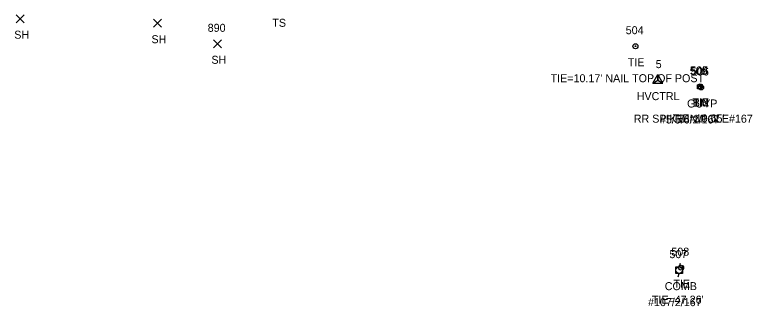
# Model space of a CAD drawing. Extents: x 1879695 to 1880991, y 836466 to 845172.
# Drawn here: x 1880139.2 to 1880323.5, y 843938.5 to 844011.4 of the extents above; entities that cross this region are included whole.
import ezdxf

# ---------------------------------------------------------------- set-up
doc = ezdxf.new("R2010")
doc.units = 0
for name, color, linetype in [('C_A', 7, 'Continuous'), ('C_C', 7, 'Continuous'), ('C_I', 7, 'Continuous'), ('CBP', 7, 'Continuous'), ('CPBM', 7, 'Continuous'), ('CPSM', 7, 'Continuous'), ('L_A', 7, 'Continuous'), ('L_I', 7, 'Continuous'), ('L_TIC', 7, 'Continuous'), ('U_A', 7, 'Continuous'), ('U_C', 7, 'Continuous'), ('U_I', 7, 'Continuous'), ('UP', 7, 'Continuous'), ('UPGW', 7, 'Continuous')]:
    doc.layers.add(name, color=color, linetype=linetype)

msp = doc.modelspace()

# ---------------------------------------------------------------- linework, layer by layer
at = {"layer": 'CBP'}
for centre, radius in [((1880294.29, 844003.49), 0.625), ((1880294.29, 844003.49), 0.0833), ((1880310.44, 843993.45), 0.625), ((1880310.44, 843993.45), 0.0833), ((1880305.7, 843948.11), 0.625), ((1880305.7, 843948.11), 0.0833)]:
    msp.add_circle(centre, radius, dxfattribs=at)
at = {"layer": 'CPBM'}
for p, q in [((1880309.8, 843992.87), (1880309.8, 843993.87)), ((1880309.8, 843993.87), (1880310.8, 843993.87)), ((1880310.8, 843992.87), (1880309.8, 843992.87)), ((1880310.3, 843993.37), (1880310.3, 843993.37)), ((1880310.3, 843993.37), (1880310.3, 843993.37)), ((1880310.8, 843993.87), (1880310.8, 843992.87))]:
    msp.add_line(p, q, dxfattribs=at)
at = {"layer": 'CPSM'}
for p, q in [((1880298.66, 843994.29), (1880299.91, 843996.46)), ((1880301.16, 843994.29), (1880299.91, 843996.46)), ((1880299.91, 843995.01), (1880299.91, 843996.46)), ((1880298.66, 843994.29), (1880299.91, 843995.01)), ((1880298.66, 843994.29), (1880301.16, 843994.29)), ((1880299.91, 843995.01), (1880299.91, 843995.01)), ((1880299.91, 843995.01), (1880301.16, 843994.29))]:
    msp.add_line(p, q, dxfattribs=at)
at = {"layer": 'L_TIC'}
for points in [[(1880139.57, 844009.37), (1880141.57, 844011.37)], [(1880141.57, 844009.37), (1880139.57, 844011.37)], [(1880173.86, 844008.24), (1880175.86, 844010.24)], [(1880175.86, 844008.24), (1880173.86, 844010.24)], [(1880188.85, 844003.1), (1880190.85, 844005.1)], [(1880190.85, 844003.1), (1880188.85, 844005.1)]]:
    msp.add_lwpolyline(points, dxfattribs=at)
at = {"layer": 'UP'}
for p, q in [((1880304.39, 843946.66), (1880304.39, 843948.32)), ((1880304.39, 843948.32), (1880306.05, 843948.32)), ((1880305.47, 843949.16), (1880305.22, 843948.32)), ((1880306.05, 843948.32), (1880306.05, 843946.66)), ((1880306.05, 843946.66), (1880304.39, 843946.66)), ((1880304.97, 843945.82), (1880305.22, 843946.66)), ((1880305.22, 843947.49), (1880305.22, 843947.49))]:
    msp.add_line(p, q, dxfattribs=at)
msp.add_circle((1880305.22, 843947.49), 0.833, dxfattribs=at)
at = {"layer": 'UPGW'}
for radius in [0.625, 0.0833]:
    msp.add_circle((1880310.67, 843993.17), radius, dxfattribs=at)

# ---------------------------------------------------------------- texts
at = {"layer": 'C_A'}
for s, p in [('TIE', (1880292.37, 843998.49)), ('HVCTRL', (1880294.6, 843990.01)), ('TIE', (1880308.52, 843988.45)), ('BM', (1880308.61, 843988.37)), ('TIE', (1880303.77, 843943.11))]:
    msp.add_text(s, height=2, dxfattribs=at).set_placement(p)
at = {"layer": 'C_C'}
for s, p in [("TIE=10.17' NAIL TOP OF POST", (1880273.09, 843994.49)), ('RR SPIKE IN POLE#167', (1880293.87, 843984.37)), ("TIE=10.65'", (1880303.62, 843984.45)), ("TIE=47.26'", (1880298.39, 843939.11))]:
    msp.add_text(s, height=2, dxfattribs=at).set_placement(p)
at = {"layer": 'C_I'}
for s, p in [('504', (1880291.85, 844006.49)), ('5', (1880299.34, 843998.01)), ('509', (1880307.85, 843996.37)), ('505', (1880308, 843996.45)), ('508', (1880303.25, 843951.11))]:
    msp.add_text(s, height=2, dxfattribs=at).set_placement(p)
at = {"layer": 'L_A'}
for s, p in [('TS', (1880203.55, 844008.35)), ('SH', (1880139.06, 844005.37)), ('SH', (1880173.35, 844004.24)), ('SH', (1880188.33, 843999.1))]:
    msp.add_text(s, height=2, dxfattribs=at).set_placement(p)
at = {"layer": 'L_I'}
msp.add_text('890', height=2, dxfattribs=at).set_placement((1880187.4, 844007.1))
at = {"layer": 'U_A'}
for s, p in [('GUYP', (1880307.18, 843988.17)), ('COMB', (1880301.61, 843942.49))]:
    msp.add_text(s, height=2, dxfattribs=at).set_placement(p)
at = {"layer": 'U_C'}
for s, p in [('#5/5/6/2/167', (1880300.39, 843984.17)), ('#107/2/167', (1880297.43, 843938.49))]:
    msp.add_text(s, height=2, dxfattribs=at).set_placement(p)
at = {"layer": 'U_I'}
for s, p in [('506', (1880308.18, 843996.17)), ('507', (1880302.78, 843950.49))]:
    msp.add_text(s, height=2, dxfattribs=at).set_placement(p)

doc.saveas('drawing.dxf')
